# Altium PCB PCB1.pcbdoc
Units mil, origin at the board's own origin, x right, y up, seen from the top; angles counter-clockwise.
Board outline 3937 x 3937 mil, 2 copper layers (Top Layer, Bottom Layer), stack 62.2 mil thick; 14 components, 17 nets, 84 pads, 0 vias.
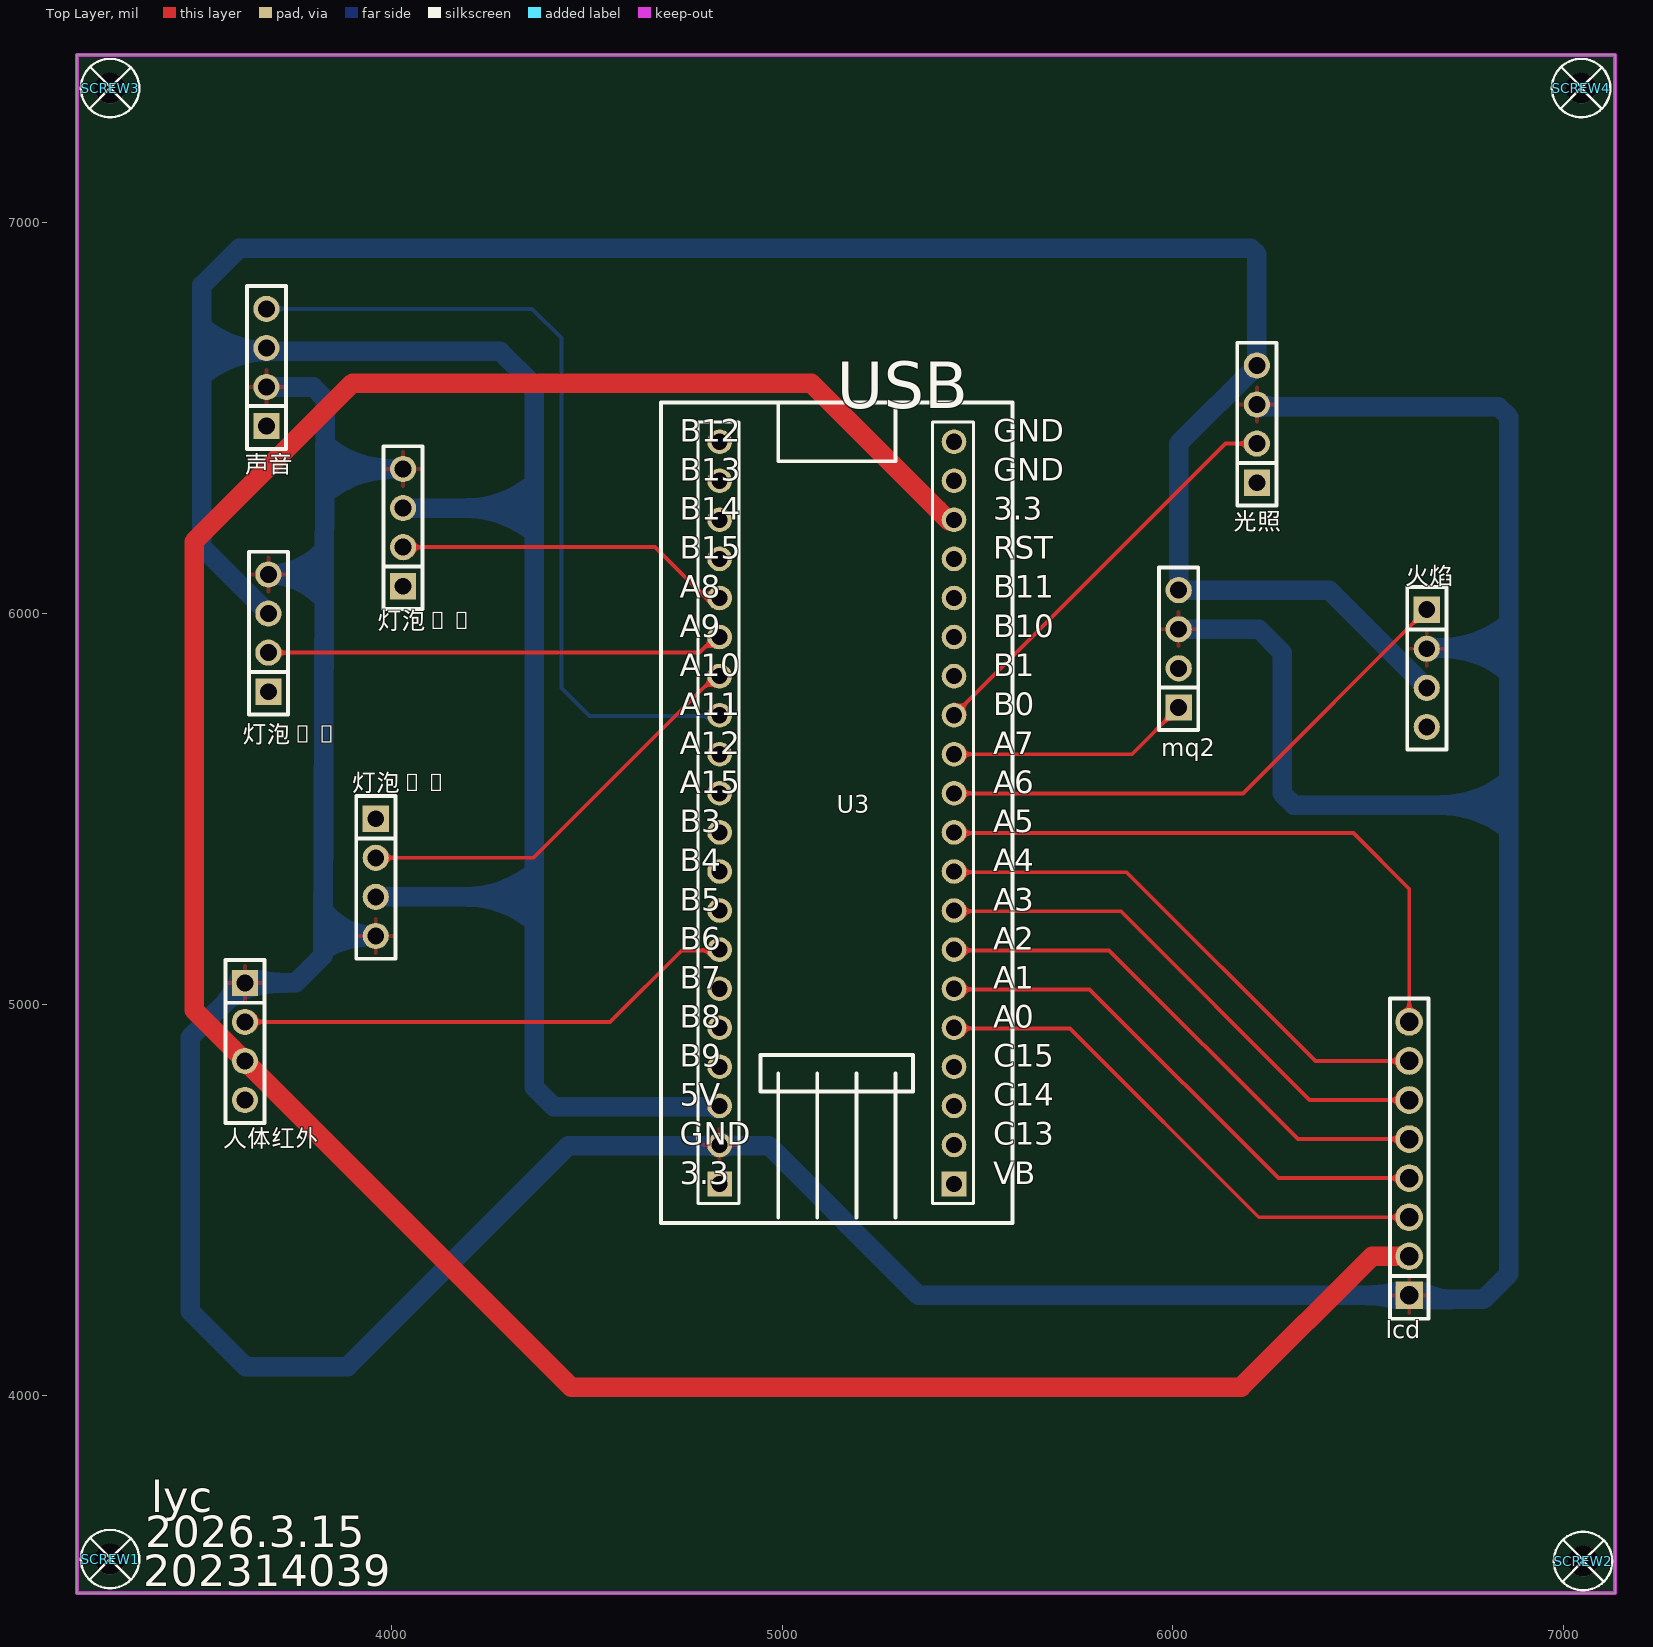
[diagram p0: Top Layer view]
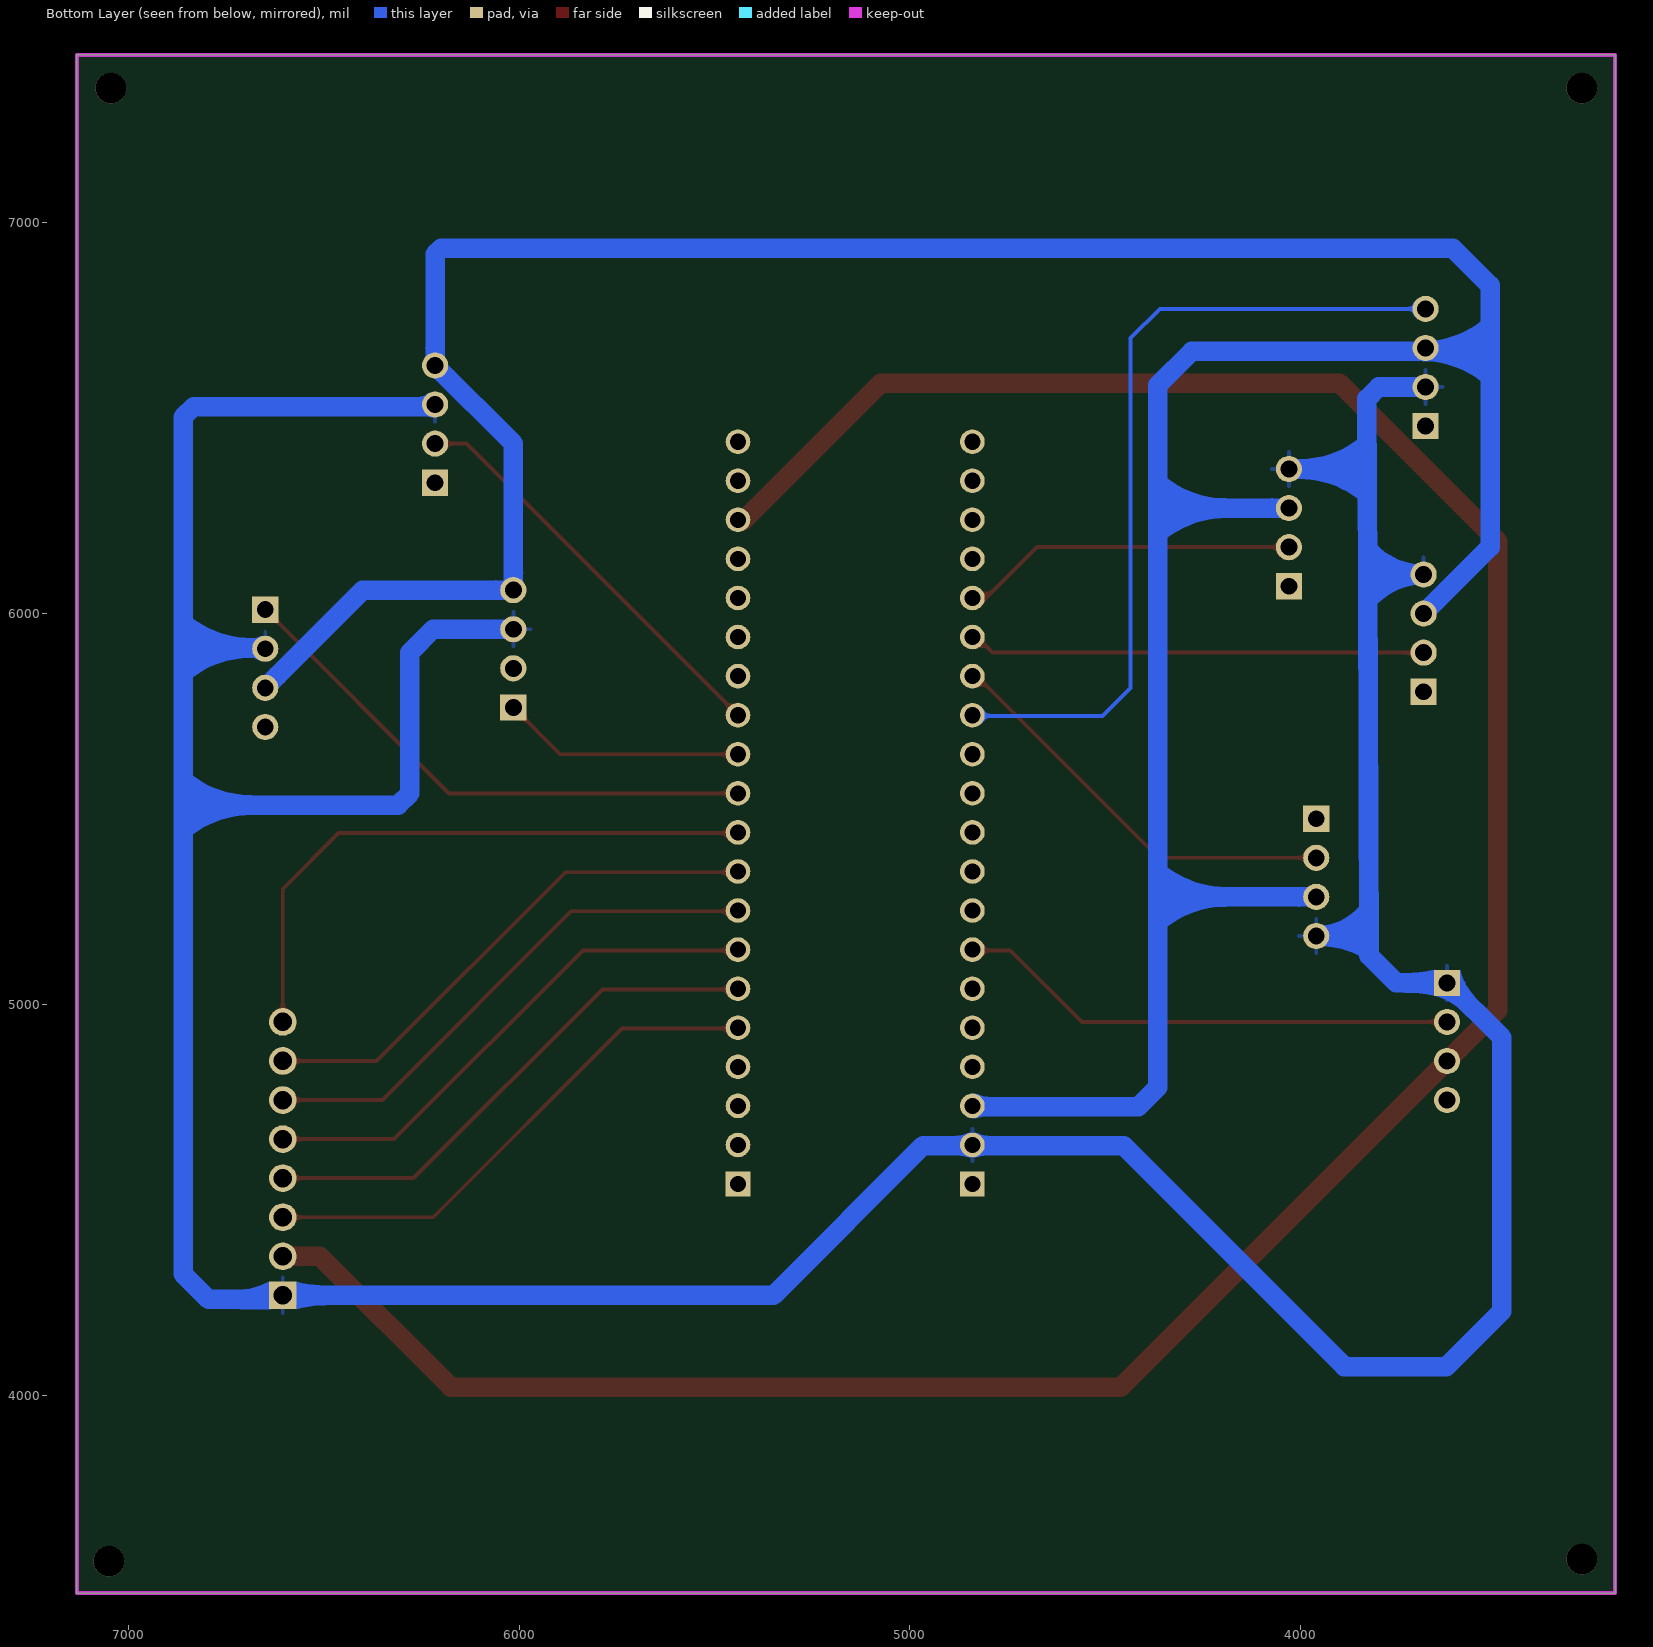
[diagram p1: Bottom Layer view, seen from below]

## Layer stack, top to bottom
Top Solder Mask Layer: solder mask 0.4, Dk 3.3
Top Layer: signal copper 1.4
Dielectric1: surface 59.4, FR4, Dk 4.5
Bottom Layer: signal copper 1.4
Bottom Solder Mask Layer: solder mask 0.4, Dk 3.3

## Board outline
3195,7430 3195,3493 7132,3493 7132,7430

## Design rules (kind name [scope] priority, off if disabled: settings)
BoardOutlineClearance copperThickness1oz [All] p0: genericclearance=10 ignorepadtopadclearanceinfootprint=FALSE except(0: Arc-SplitContinuation Track-SplitContinuation SMDPad-SplitContinuation THPad-SplitContinuation Via-SplitContinuation Fill-SplitContinuation Poly-SplitContinuation Region-SplitContinuation Text-SplitContinuation)
BoardOutlineClearance copperThickness2oz [All] p0: genericclearance=10 ignorepadtopadclearanceinfootprint=FALSE except(0: Arc-SplitContinuation Track-SplitContinuation SMDPad-SplitContinuation THPad-SplitContinuation Via-SplitContinuation Fill-SplitContinuation Poly-SplitContinuation Region-SplitContinuation Text-SplitContinuation)
BoardOutlineClearance Plane_innerPlane [All] p0: genericclearance=10 ignorepadtopadclearanceinfootprint=FALSE except(0: Arc-SplitContinuation Track-SplitContinuation SMDPad-SplitContinuation THPad-SplitContinuation Via-SplitContinuation Fill-SplitContinuation Poly-SplitContinuation Region-SplitContinuation Text-SplitContinuation)
BoardOutlineClearance Copper_copperRegion [All] p0: genericclearance=10 ignorepadtopadclearanceinfootprint=FALSE except(0: Arc-SplitContinuation Track-SplitContinuation SMDPad-SplitContinuation THPad-SplitContinuation Via-SplitContinuation Fill-SplitContinuation Poly-SplitContinuation Region-SplitContinuation Text-SplitContinuation)
BoardOutlineClearance otherClearance [All] p0: genericclearance=10 ignorepadtopadclearanceinfootprint=FALSE except(0: Arc-SplitContinuation Track-SplitContinuation SMDPad-SplitContinuation THPad-SplitContinuation Via-SplitContinuation Fill-SplitContinuation Poly-SplitContinuation Region-SplitContinuation Text-SplitContinuation)
Clearance copperThickness1oz [All] p1: gap=7 ignorepadtopadclearanceinfootprint=FALSE
Clearance copperThickness2oz [All] p1: gap=7 ignorepadtopadclearanceinfootprint=FALSE
Clearance Plane_innerPlane [All] p1: gap=7 ignorepadtopadclearanceinfootprint=FALSE
Clearance Copper_copperRegion [All] p1: gap=7 ignorepadtopadclearanceinfootprint=FALSE
Clearance otherClearance [All] p1: gap=7 ignorepadtopadclearanceinfootprint=FALSE
DiffPairsRouting differentialPair [All] p1: maxuncoupledlength=10 minlimit=6 maxlimit=Infinity mostfreqgap=6 toplayer_minwidth=5 toplayer_prefwidth=10 toplayer_maxwidth=100 bottomlayer_minwidth=5 bottomlayer_prefwidth=10 bottomlayer_maxwidth=100
PasteMaskExpansion pasteMaskExpansion [All] p1: expansion=0
PlaneConnect innerPlane [All] p1: planeconnectstyle=Relief reliefexpansion=20 reliefentries=4 reliefconductorwidth=10 reliefairgap=10
PolygonConnect copperRegion [All] p1: connectstyle=Relief reliefentries=4 reliefconductorwidth=10 polygonreliefangle="90 Angle" airgapwidth=10
RoutingVias viaSize [All] p1: viastyle="Through Hole" holewidth=12.0078 minholewidth=11.811 maxholewidth=248.0314 width=12.0078 minwidth=11.811 maxwidth=248.0314
SolderMaskExpansion solderMaskExpansion [IsVia] p1: useseparateexpansions=TRUE expansion=-1000 expansionbottom=-1000
SolderMaskExpansion solderMaskExpansion [All] p2: useseparateexpansions=TRUE expansion=2 expansionbottom=2
Width copperThickness1oz [All] p1: maxlimit=100 minlimit=5 preferedwidth=10
Width copperThickness2oz [All] p1: maxlimit=100 minlimit=8 preferedwidth=10

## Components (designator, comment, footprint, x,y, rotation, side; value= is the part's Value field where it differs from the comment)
lcd "lcd" HDR-TH_8P-P2.54-V-F-1 6605,4605 r90 top
mq2 "2.54-1*4P母" HDR-TH_4P-P2.54-V-F 6015,5910 r90 top
SCREW1 "" M2螺丝 3280,3580 r0 top
SCREW2 "" M2螺丝 7050,3575 r0 top
SCREW3 "" M2螺丝 3280,7345 r0 top
SCREW4 "" M2螺丝 7045,7345 r0 top
U3 "CW32F030C8最小系统板" STM32F103C8T6核心板 5140,5490 r0 top
人体红外 "2.54-1*4P母" HDR-TH_4P-P2.54-V-F 3625,4905 r270 top
光照 "光照" HDR-TH_4P-P2.54-V-F 6215,6485 r90 top
声音 "2.54-1*4P母" HDR-TH_4P-P2.54-V-F 3680,6630 r90 top
火焰 "火焰" HDR-TH_4P-P2.54-V-F 6650,5860 r270 top
灯泡-1 "2.54-1*4P母" HDR-TH_4P-P2.54-V-F 3960,5325 r270 top
灯泡-2 "2.54-1*4P母" HDR-TH_4P-P2.54-V-F 3685,5950 r90 top
灯泡-3 "2.54-1*4P母" HDR-TH_4P-P2.54-V-F 4030,6220 r90 top

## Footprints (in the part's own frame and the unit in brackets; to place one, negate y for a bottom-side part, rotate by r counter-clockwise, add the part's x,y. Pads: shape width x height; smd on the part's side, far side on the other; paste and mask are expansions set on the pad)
HDR-TH_4P-P2.54-V-F [mil]
  rect 66.9x66.9 hole 43.3: 1(-150,0)
  round 66.9 hole 43.3: 2(-50,0) 3(50,0) 4(150,0)
  silkscreen extent -208,-50 208,50
HDR-TH_8P-P2.54-V-F-1 [mil]
  rect 70.9x70.9 hole 47.2: 1(-350,0)
  round 70.9 hole 47.2: 2(-250,0) 3(-150,0) 4(-50,0) 5(50,0) 6(150,0) 7(250,0) 8(350,0)
  silkscreen extent -410,-49 410,49
M2螺丝 [mil]
  round 78.7 hole 78.7: 1(0,0)
  silkscreen extent -75,-75 75,75
STM32F103C8T6核心板 [mil]
  rect 63x63 hole 41.3 paste+4 mask+4: 1(300,-950) 40(-300,-950)
  round 63 hole 41.3 paste+4 mask+4: 2(300,-850) 3(300,-750) 4(300,-650) 5(300,-550) 6(300,-450) 7(300,-350) 8(300,-250) 9(300,-150) 10(300,-50) 11(300,50) 12(300,150) 13(300,250) 14(300,350) 15(300,450) 16(300,550) 17(300,650) 18(300,750) 19(300,850) 20(300,950) 21(-300,950) 22(-300,850) 23(-300,750) 24(-300,650) 25(-300,550) 26(-300,450) 27(-300,350) 28(-300,250) 29(-300,150) 30(-300,50) 31(-300,-50) 32(-300,-150) 33(-300,-250) 34(-300,-350) 35(-300,-450) 36(-300,-550) 37(-300,-650) 38(-300,-750) 39(-300,-850)
  silkscreen extent -450,-1050 450,1050

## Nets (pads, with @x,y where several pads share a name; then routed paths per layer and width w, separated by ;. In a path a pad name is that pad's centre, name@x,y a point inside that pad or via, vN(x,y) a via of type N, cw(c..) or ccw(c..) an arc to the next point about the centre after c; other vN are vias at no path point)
AO: mq2.1 U3.12 | length 624.7
  Top Layer w10: U3.12 5895,5640 mq2.1
BLK: lcd.8 U3.10 | length 1578.1
  Top Layer w10: U3.10@5426.2,5438.1 6461.9,5438.1 6605,5295 lcd.8
CS: lcd.7 U3.9 | length 1378.9
  Top Layer w10: U3.9@5426.2,5338.1 5881.9,5338.1 6365,4855 lcd.7
DC: lcd.6 U3.8 | length 1378.9
  Top Layer w10: U3.8@5426.2,5238.1 5866.9,5238.1 6350,4755 lcd.6
DO-1: U3.13 光照.2 | length 1062.9
  Top Layer w10: U3.13 6135,6435 光照.2
DO-2: U3.34 人体红外.2 | length 1277
  Top Layer w10: 人体红外.2 4559.8,4955 4743,5138.1 U3.34@4826.2,5138.1
DO-3: U3.11 火焰.1 | length 1404.7
  Top Layer w10: U3.11 6180,5540 火焰.1
DO-4: U3.28 声音.4 | length 2102
  Bottom Layer w10: 声音.4 4360,6780 4435,6705 4435,5810 4506.9,5738.1 U3.28@4826.2,5738.1
GND: lcd.1 mq2.3 U3.39 人体红外.1 光照.3 声音.2 火焰.2 灯泡-1.4 灯泡-2.4 灯泡-3.4 | length 11343.7
  Bottom Layer w50: 声音.2 3800,6580 3830.5,6549.5 3828.7,6099 ; 灯泡-2.4 3827.7,6100 3828.7,6099 ; 3835,5185 3845,5175 灯泡-1.4 ; 3840,6370 灯泡-3.4 ; mq2.3 6220,5960 6280,5900 6280,5540 6310,5510 6853,5510 6860,5517 ; 光照.3 6220,6530 6832.9,6530 6860,6502.9 6860,5910 ; 火焰.2 6652.1,5912.1 6857.9,5912.1 6860,5910 ; 3828.7,6099 3824.9,5124.9 3755,5055 人体红外.1 3485,4915 3485,4215 3627.1,4072.9 3887.9,4072.9 4453.1,4638.1 4826.2,4638.1 4966.2,4638.1 5349.4,4255 lcd.1 6615,4245 6795,4245 6860,4310 6860,5517 ; 6860,5517 6860,5910
PA8: U3.25 灯泡-3.2 | length 845
  Top Layer w10: 灯泡-3.2 4674.5,6170 U3.25@4816.3,6028.2
PA9: U3.26 灯泡-2.2 | length 1157
  Top Layer w10: 灯泡-2.2 4788.1,5900 U3.26@4826.2,5938.1
PA10: U3.27 灯泡-1.2 | length 1044
  Top Layer w10: 灯泡-1.2 4363.1,5375 U3.27@4816.3,5828.2
RES: lcd.5 U3.7 | length 1378.9
  Top Layer w10: U3.7@5426.2,5138.1 5836.9,5138.1 6320,4655 lcd.5
SCL: lcd.3 U3.5 | length 1378.9
  Top Layer w10: U3.5@5426.2,4938.1 5736.9,4938.1 6220,4455 lcd.3
SDA: lcd.4 U3.6 | length 1378.9
  Top Layer w10: U3.6@5426.2,5038.1 5786.9,5038.1 6270,4555 lcd.4
VCC-3: lcd.2 U3.18 人体红外.3 | length 7092.8
  Top Layer w50: U3.18@5426.2,6238.1 5074.4,6590 3900.7,6590 3495,6184.3 3495,4985 人体红外.3 4460,4020 6175,4020 6510,4355 lcd.2
VCC-5: mq2.4 U3.38 光照.4 声音.3 火焰.3 灯泡-1.3 灯泡-2.3 灯泡-3.3 | length 9263.8
  Bottom Layer w10: 声音.3 声音.3@3688.5,6671.5
  Bottom Layer w50: 灯泡-2.3 3515,6170 3515,6671.5 ; 灯泡-1.3 4352.6,5275 4365,5262.6 ; 灯泡-3.3 4353.8,6270 4365,6258.8 ; U3.38@4826.2,4738.1 4415,4738.1 4365,4788.1 4365,5262.6 ; 火焰.3 6400,6060 mq2.4 6015,6435 光照.4 6215,6920 6200,6935 3610,6935 3515,6840 3515,6671.5 ; 3515,6671.5 3688.5,6671.5 4278.5,6671.5 4365,6585 4365,6258.8 ; 4365,5262.6 4365,6258.8
pads on no net: mq2.2 SCREW1.1 SCREW2.1 SCREW3.1 SCREW4.1 U3.1 U3.2 U3.3 U3.4 U3.14 U3.15 U3.16 U3.17 U3.19 U3.20 U3.21 U3.22 U3.23 U3.24 U3.29 U3.30 U3.31 U3.32 U3.33 U3.35 U3.36 U3.37 U3.40 人体红外.4 光照.1 声音.1 火焰.4 灯泡-1.1 灯泡-2.1 灯泡-3.1

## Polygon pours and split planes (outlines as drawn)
GND on Top Layer (solid, remove dead copper, pour order 0): 3035,7515 3035,3265 7390,3265 7390,7515
GND on Bottom Layer (solid, remove dead copper, pour order 2): 3000,7655 3000,3000 7655,3000 7655,7655

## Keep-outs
Board Outline Layer:
  the board outline again, w10

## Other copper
Top Layer:
  region net DO-2: 3670.6,4960 3670.6,4950 3667.9,4949.9 3665.7,4949.5 3663.7,4949 3662.1,4948.3 3660.7,4947.4 3659.5,4946.3 3658.4,4945.1 3657.4,4943.7 3653.5,4937.3 3650.8,4933.7 3649.1,4931.8 3647.1,4929.9 3647.1,4980.1 3649.1,4978.2 3650.8,4976.3 3653.5,4972.7 3657.4,4966.3 3658.4,4964.9 3659.5,4963.7 3660.7,4962.6 3662.1,4961.7 3663.7,4961 3665.7,4960.5 3667.9,4960.1
  region net VCC-3: 3575.1,4869.5 3610.5,4904.9 3611.9,4903.4 3613.1,4901.8 3614.9,4898.9 3617.5,4893.8 3618.9,4891.8 3619.7,4890.9 3620.7,4890.1 3621.9,4889.5 3623.4,4889 3625.1,4888.6 3627.1,4888.4 3591.6,4852.9 3591.4,4854.9 3591,4856.6 3590.5,4858.1 3589.9,4859.3 3589.1,4860.3 3588.2,4861.1 3586.2,4862.5 3581.1,4865.1 3578.2,4866.9 3576.6,4868.1
  region net VCC-3: 3674.9,4840.5 3639.5,4805.1 3638.1,4806.6 3636.9,4808.2 3635.1,4811.1 3632.5,4816.2 3631.1,4818.2 3630.3,4819.1 3629.3,4819.9 3628.1,4820.5 3626.6,4821 3624.9,4821.4 3622.9,4821.6 3658.4,4857.1 3658.6,4855.1 3659,4853.4 3659.5,4851.9 3660.1,4850.7 3660.9,4849.7 3661.8,4848.9 3663.8,4847.5 3668.9,4844.9 3671.8,4843.1 3673.4,4841.9
  region net PA9: 3730.6,5905 3730.6,5895 3727.9,5894.9 3725.7,5894.5 3723.7,5894 3722.1,5893.3 3720.7,5892.4 3719.5,5891.3 3718.4,5890.1 3717.4,5888.7 3713.5,5882.3 3710.8,5878.7 3709.1,5876.8 3707.1,5874.9 3707.1,5925.1 3709.1,5923.2 3710.8,5921.3 3713.5,5917.7 3717.4,5911.3 3718.4,5909.9 3719.5,5908.7 3720.7,5907.6 3722.1,5906.7 3723.7,5906 3725.7,5905.5 3727.9,5905.1
  region net AO: 5983.3,5721.2 5976.2,5728.3 ccw(c5955,5744.2) 5981.5,5744.2 5999.2,5726.5 ccw(c5999.2,5700) 5983.3,5721.2
  region net DO-3: 6618.3,5971.2 6611.2,5978.3 ccw(c6590,5994.2) 6616.5,5994.2 6634.2,5976.5 ccw(c6634.2,5950) 6618.3,5971.2
  region net DO-1: 6169.4,6430 6169.4,6440 6172.1,6440.1 6174.3,6440.5 6176.3,6441 6177.9,6441.7 6179.3,6442.6 6180.5,6443.7 6181.6,6444.9 6182.6,6446.3 6186.5,6452.7 6189.2,6456.3 6190.9,6458.2 6192.9,6460.1 6192.9,6409.9 6190.9,6411.8 6189.2,6413.7 6186.5,6417.3 6182.6,6423.7 6181.6,6425.1 6180.5,6426.3 6179.3,6427.4 6177.9,6428.3 6176.3,6429 6174.3,6429.5 6172.1,6429.9
  region net VCC-3: 6556.8,4330 6556.8,4380 6560.8,4379.8 6564.3,4379.2 6567.4,4378.5 6570.2,4377.9 6573,4377.7 6574.3,4377.8 6575.7,4378.1 6577.1,4378.6 6578.5,4379.3 6580,4380.3 6581.6,4381.6 6581.6,4328.4 6580,4329.7 6578.5,4330.7 6577.1,4331.4 6575.7,4331.9 6574.3,4332.2 6573,4332.3 6570.2,4332.1 6567.4,4331.5 6564.3,4330.8 6560.8,4330.2
  region net SCL: 6556.8,4450 6556.8,4460 6559.6,4460.1 6562,4460.5 6564.1,4461.1 6565.8,4461.9 6567.3,4462.8 6568.5,4464 6569.7,4465.3 6570.7,4466.7 6574.8,4473.7 6576.1,4475.6 6577.7,4477.6 6579.4,4479.6 6581.6,4481.6 6581.6,4428.4 6579.4,4430.4 6577.7,4432.4 6576.1,4434.4 6574.8,4436.3 6570.7,4443.3 6569.7,4444.7 6568.5,4446 6567.3,4447.2 6565.8,4448.1 6564.1,4448.9 6562,4449.5 6559.6,4449.9
  region net SDA: 6556.8,4550 6556.8,4560 6559.6,4560.1 6562,4560.5 6564.1,4561.1 6565.8,4561.9 6567.3,4562.8 6568.5,4564 6569.7,4565.3 6570.7,4566.7 6574.8,4573.7 6576.1,4575.6 6577.7,4577.6 6579.4,4579.6 6581.6,4581.6 6581.6,4528.4 6579.4,4530.4 6577.7,4532.4 6576.1,4534.4 6574.8,4536.3 6570.7,4543.3 6569.7,4544.7 6568.5,4546 6567.3,4547.2 6565.8,4548.1 6564.1,4548.9 6562,4549.5 6559.6,4549.9
  region net RES: 6556.8,4650 6556.8,4660 6559.6,4660.1 6562,4660.5 6564.1,4661.1 6565.8,4661.9 6567.3,4662.8 6568.5,4664 6569.7,4665.3 6570.7,4666.7 6574.8,4673.7 6576.1,4675.6 6577.7,4677.6 6579.4,4679.6 6581.6,4681.6 6581.6,4628.4 6579.4,4630.4 6577.7,4632.4 6576.1,4634.4 6574.8,4636.3 6570.7,4643.3 6569.7,4644.7 6568.5,4646 6567.3,4647.2 6565.8,4648.1 6564.1,4648.9 6562,4649.5 6559.6,4649.9
  region net DC: 6556.8,4750 6556.8,4760 6559.6,4760.1 6562,4760.5 6564.1,4761.1 6565.8,4761.9 6567.3,4762.8 6568.5,4764 6569.7,4765.3 6570.7,4766.7 6574.8,4773.7 6576.1,4775.6 6577.7,4777.6 6579.4,4779.6 6581.6,4781.6 6581.6,4728.4 6579.4,4730.4 6577.7,4732.4 6576.1,4734.4 6574.8,4736.3 6570.7,4743.3 6569.7,4744.7 6568.5,4746 6567.3,4747.2 6565.8,4748.1 6564.1,4748.9 6562,4749.5 6559.6,4749.9
  region net CS: 6556.8,4850 6556.8,4860 6559.6,4860.1 6562,4860.5 6564.1,4861.1 6565.8,4861.9 6567.3,4862.8 6568.5,4864 6569.7,4865.3 6570.7,4866.7 6574.8,4873.7 6576.1,4875.6 6577.7,4877.6 6579.4,4879.6 6581.6,4881.6 6581.6,4828.4 6579.4,4830.4 6577.7,4832.4 6576.1,4834.4 6574.8,4836.3 6570.7,4843.3 6569.7,4844.7 6568.5,4846 6567.3,4847.2 6565.8,4848.1 6564.1,4848.9 6562,4849.5 6559.6,4849.9
  region net BLK: 6600,5003.2 6610,5003.2 6610.1,5000.4 6610.5,4998 6611.1,4995.9 6611.9,4994.2 6612.8,4992.7 6614,4991.5 6615.3,4990.3 6616.7,4989.3 6623.7,4985.2 6625.6,4983.9 6627.6,4982.3 6629.6,4980.6 6631.6,4978.4 6578.4,4978.4 6580.4,4980.6 6582.4,4982.3 6584.4,4983.9 6586.3,4985.2 6593.3,4989.3 6594.7,4990.3 6596,4991.5 6597.2,4992.7 6598.1,4994.2 6598.9,4995.9 6599.5,4998 6599.9,5000.4
  region net SCL: 5484.2,4943.1 5481.5,4933.1 5480.1,4933 5478.7,4932.6 5477.2,4931.9 5475.7,4931 5472.8,4928.7 5469.9,4925.9 5464.3,4919.9 5461.7,4917.3 5459.4,4915.2 5462.2,4962.4 5463.9,4960.6 5465.4,4958.8 5467.8,4955.3 5469.8,4952.1 5471.7,4949.2 5472.7,4947.9 5473.8,4946.7 5475,4945.7 5476.4,4944.8 5478,4944.1 5479.8,4943.6 5481.8,4943.3
  region net SDA: 5484.2,5043.1 5481.5,5033.1 5480.1,5033 5478.7,5032.6 5477.2,5031.9 5475.7,5031 5472.8,5028.7 5469.9,5025.9 5464.3,5019.9 5461.7,5017.3 5459.4,5015.2 5462.2,5062.4 5463.9,5060.6 5465.4,5058.8 5467.8,5055.3 5469.8,5052.1 5471.7,5049.2 5472.7,5047.9 5473.8,5046.7 5475,5045.7 5476.4,5044.8 5478,5044.1 5479.8,5043.6 5481.8,5043.3
  region net RES: 5484.2,5143.1 5481.5,5133.1 5480.1,5133 5478.7,5132.6 5477.2,5131.9 5475.7,5131 5472.8,5128.7 5469.9,5125.9 5464.3,5119.9 5461.7,5117.3 5459.4,5115.2 5462.2,5162.4 5463.9,5160.6 5465.4,5158.8 5467.8,5155.3 5469.8,5152.1 5471.7,5149.2 5472.7,5147.9 5473.8,5146.7 5475,5145.7 5476.4,5144.8 5478,5144.1 5479.8,5143.6 5481.8,5143.3
  region net DC: 5484.2,5243.1 5481.5,5233.1 5480.1,5233 5478.7,5232.6 5477.2,5231.9 5475.7,5231 5472.8,5228.7 5469.9,5225.9 5464.3,5219.9 5461.7,5217.3 5459.4,5215.2 5462.2,5262.4 5463.9,5260.6 5465.4,5258.8 5467.8,5255.3 5469.8,5252.1 5471.7,5249.2 5472.7,5247.9 5473.8,5246.7 5475,5245.7 5476.4,5244.8 5478,5244.1 5479.8,5243.6 5481.8,5243.3
  region net CS: 5484.2,5343.1 5481.5,5333.1 5480.1,5333 5478.7,5332.6 5477.2,5331.9 5475.7,5331 5472.8,5328.7 5469.9,5325.9 5464.3,5319.9 5461.7,5317.3 5459.4,5315.2 5462.2,5362.4 5463.9,5360.6 5465.4,5358.8 5467.8,5355.3 5469.8,5352.1 5471.7,5349.2 5472.7,5347.9 5473.8,5346.7 5475,5345.7 5476.4,5344.8 5478,5344.1 5479.8,5343.6 5481.8,5343.3
  region net BLK: 5484.2,5443.1 5481.5,5433.1 5480.1,5433 5478.7,5432.6 5477.2,5431.9 5475.7,5431 5472.8,5428.7 5469.9,5425.9 5464.3,5419.9 5461.7,5417.3 5459.4,5415.2 5462.2,5462.4 5463.9,5460.6 5465.4,5458.8 5467.8,5455.3 5469.8,5452.1 5471.7,5449.2 5472.7,5447.9 5473.8,5446.7 5475,5445.7 5476.4,5444.8 5478,5444.1 5479.8,5443.6 5481.8,5443.3
  region net DO-3: 5482.9,5545 5482.9,5535 5480.4,5534.9 5478.3,5534.6 5476.5,5534.1 5475,5533.4 5473.7,5532.6 5472.5,5531.6 5471.5,5530.4 5470.5,5529.2 5466.8,5523.2 5464.2,5519.8 5462.7,5518.1 5460.8,5516.4 5460.8,5563.6 5462.7,5561.9 5464.2,5560.2 5466.8,5556.8 5470.5,5550.8 5471.5,5549.6 5472.5,5548.4 5473.7,5547.4 5475,5546.6 5476.5,5545.9 5478.3,5545.4 5480.4,5545.1
  region net AO: 5482.9,5645 5482.9,5635 5480.4,5634.9 5478.3,5634.6 5476.5,5634.1 5475,5633.4 5473.7,5632.6 5472.5,5631.6 5471.5,5630.4 5470.5,5629.2 5466.8,5623.2 5464.2,5619.8 5462.7,5618.1 5460.8,5616.4 5460.8,5663.6 5462.7,5661.9 5464.2,5660.2 5466.8,5656.8 5470.5,5650.8 5471.5,5649.6 5472.5,5648.4 5473.7,5647.4 5475,5646.6 5476.5,5645.9 5478.3,5645.4 5480.4,5645.1
  region net DO-1: 5466.8,5773.9 5473.9,5766.8 5472.2,5765 5470.9,5763.3 5470,5761.6 5469.4,5760.1 5469.1,5758.5 5469,5757 5469,5755.5 5469.2,5753.9 5470.8,5747 5471.4,5742.9 5471.5,5740.6 5471.4,5738 5438,5771.4 5440.6,5771.5 5442.9,5771.4 5447,5770.8 5453.9,5769.2 5455.5,5769 5457,5769 5458.5,5769.1 5460.1,5769.4 5461.6,5770 5463.3,5770.9 5465,5772.2
  region net VCC-3: 5389.1,6240 5414.8,6285 5416.1,6283.5 5417.2,6282.1 5419.1,6279.1 5422,6273.7 5423.5,6271.6 5424.4,6270.8 5425.4,6270.2 5426.5,6269.9 5427.9,6269.7 5429.4,6269.8 5431.2,6270.2 5410.2,6229.9 5409.5,6231.4 5408.7,6232.6 5407.7,6233.6 5406.5,6234.3 5405.3,6234.9 5403.9,6235.3 5401,6235.8 5397.9,6236.2 5394.7,6236.8 5393.2,6237.3 5391.8,6238 5390.4,6238.8
  region net PA8: 4807.5,6030 4788,6063.6 4791.3,6060.8 4793,6059.5 4794.8,6058.4 4796.7,6057.5 4798.5,6056.7 4800.4,6056.1 4802.3,6055.7 4804.2,6055.5 4806.1,6055.5 4807.9,6055.7 4809.7,6056.2 4811.4,6056.9 4813.1,6057.9 4814.7,6059.1 4816.2,6060.6 4822.5,6013.8 4820.5,6015.3 4818.5,6017.2 4814.7,6021.5 4811.1,6026
  region net PA9: 4803.3,5908.2 4805.2,5924.2 4806.2,5925.4 4807,5926.7 4807.7,5928.1 4808.1,5929.7 4808.7,5933 4808.9,5936.5 4809.1,5943.7 4809.5,5947.1 4809.8,5948.8 4810.2,5950.3 4833.5,5909.2 4829.1,5910.2 4824.9,5911.3 4820.9,5912.3 4817.1,5912.9 4815.3,5913 4813.5,5913 4811.7,5912.8 4810,5912.4 4808.3,5911.7 4806.6,5910.8 4805,5909.6
  region net PA10: 4803.3,5808.2 4805.2,5824.2 4806.2,5825.4 4807,5826.7 4807.7,5828.1 4808.1,5829.7 4808.7,5833 4808.9,5836.5 4809.1,5843.7 4809.5,5847.1 4809.8,5848.8 4810.2,5850.3 4833.5,5809.2 4829.1,5810.2 4824.9,5811.3 4820.9,5812.3 4817.1,5812.9 4815.3,5813 4813.5,5813 4811.7,5812.8 4810,5812.4 4808.3,5811.7 4806.6,5810.8 4805,5809.6
  region net DO-2: 4798.5,5133.1 4795.8,5143.1 4798.2,5143.3 4800.2,5143.6 4802,5144.1 4803.6,5144.8 4805,5145.7 4806.2,5146.7 4807.3,5147.9 4808.3,5149.2 4810.2,5152.1 4812.2,5155.3 4814.6,5158.8 4816.1,5160.6 4817.8,5162.4 4820.6,5115.2 4818.3,5117.3 4815.7,5119.9 4810.1,5125.9 4807.2,5128.7 4804.3,5131 4802.8,5131.9 4801.3,5132.6 4799.9,5133
  region net PA10: 4005.6,5380 4005.6,5370 4002.9,5369.9 4000.7,5369.5 3998.7,5369 3997.1,5368.3 3995.7,5367.4 3994.5,5366.3 3993.4,5365.1 3992.4,5363.7 3988.5,5357.3 3985.8,5353.7 3984.1,5351.8 3982.1,5349.9 3982.1,5400.1 3984.1,5398.2 3985.8,5396.3 3988.5,5392.7 3992.4,5386.3 3993.4,5384.9 3994.5,5383.7 3995.7,5382.6 3997.1,5381.7 3998.7,5381 4000.7,5380.5 4002.9,5380.1
  region net PA8: 4075.6,6175 4075.6,6165 4072.9,6164.9 4070.7,6164.5 4068.7,6164 4067.1,6163.3 4065.7,6162.4 4064.5,6161.3 4063.4,6160.1 4062.4,6158.7 4058.5,6152.3 4055.8,6148.7 4054.1,6146.8 4052.1,6144.9 4052.1,6195.1 4054.1,6193.2 4055.8,6191.3 4058.5,6187.7 4062.4,6181.3 4063.4,6179.9 4064.5,6178.7 4065.7,6177.6 4067.1,6176.7 4068.7,6176 4070.7,6175.5 4072.9,6175.1
Bottom Layer:
  region net GND: 3733.5,5080 3733.5,5030 ccw(c3733.5,4693.5) 3658.5,5021.5 3658.5,5088.5 ccw(c3733.5,5416.5) 3733.5,5080
  region net GND: 3589.6,4984.3 3554.3,5019.6 ccw(c3457.3,5116.6) 3591.5,5088.5 3658.5,5021.5 ccw(c3686.6,4887.3) 3589.6,4984.3
  region net VCC-5: 3635.1,6014.5 3670.5,6049.9 3671.9,6048.4 3673.1,6046.8 3674.9,6043.9 3677.5,6038.8 3678.9,6036.8 3679.7,6035.9 3680.7,6035.1 3681.9,6034.5 3683.4,6034 3685.1,6033.6 3687.1,6033.4 3651.6,5997.9 3651.4,5999.9 3651,6001.6 3650.5,6003.1 3649.9,6004.3 3649.1,6005.3 3648.2,6006.1 3646.2,6007.5 3641.1,6010.1 3638.2,6011.9 3636.6,6013.1
  region net GND: 3730.6,6125 3730.6,6075 3728.5,6075.1 3726.6,6075.3 3723.2,6076.1 3717.8,6077.8 3715.3,6078.3 3714.1,6078.3 3712.8,6078.2 3711.5,6077.8 3710.2,6077.1 3708.7,6076.2 3707.1,6074.9 3707.1,6125.1 3708.7,6123.8 3710.2,6122.9 3711.5,6122.2 3712.8,6121.8 3714.1,6121.7 3715.3,6121.7 3717.8,6122.2 3723.2,6123.9 3726.6,6124.7 3728.5,6124.9
  region net GND: 3725.6,6605 3725.6,6555 3723.5,6555.1 3721.6,6555.3 3718.2,6556.1 3712.8,6557.8 3710.3,6558.3 3709.1,6558.3 3707.8,6558.2 3706.5,6557.8 3705.2,6557.1 3703.7,6556.2 3702.1,6554.9 3702.1,6605.1 3703.7,6603.8 3705.2,6602.9 3706.5,6602.2 3707.8,6601.8 3709.1,6601.7 3710.3,6601.7 3712.8,6602.2 3718.2,6603.9 3721.6,6604.7 3723.5,6604.9
  region net VCC-5: 3732.5,6696.5 3719.9,6646.5 3718.4,6646.6 3717,6646.8 3713.9,6647.7 3707.8,6650.1 3704.8,6651.2 3701.9,6651.8 3700.5,6651.9 3699.1,6651.8 3697.8,6651.5 3696.5,6650.9 3709.1,6696.6 3710.2,6694.9 3711.3,6693.7 3712.4,6692.8 3713.5,6692.3 3714.7,6692.1 3715.9,6692.1 3717.2,6692.3 3718.6,6692.7 3724.7,6695.1 3728.4,6696.1 3730.4,6696.4
  region net VCC-5: 3640.1,6646.5 3627.5,6696.5 3629.6,6696.4 3631.6,6696.1 3635.3,6695.1 3641.4,6692.7 3642.8,6692.3 3644.1,6692.1 3645.3,6692.1 3646.5,6692.3 3647.6,6692.8 3648.7,6693.7 3649.8,6694.9 3650.9,6696.6 3663.5,6650.9 3662.2,6651.5 3660.9,6651.8 3659.5,6651.9 3658.1,6651.8 3655.2,6651.2 3652.2,6650.1 3646.1,6647.7 3643,6646.8 3641.6,6646.6
  region net DO-4: 3725.6,6785 3725.6,6775 3722.9,6774.9 3720.7,6774.5 3718.7,6774 3717.1,6773.3 3715.7,6772.4 3714.5,6771.3 3713.4,6770.1 3712.4,6768.7 3708.5,6762.3 3705.8,6758.7 3704.1,6756.8 3702.1,6754.9 3702.1,6805.1 3704.1,6803.2 3705.8,6801.3 3708.5,6797.7 3712.4,6791.3 3713.4,6789.9 3714.5,6788.7 3715.7,6787.6 3717.1,6786.7 3718.7,6786 3720.7,6785.5 3722.9,6785.1
  region net GND: 6060.6,5985 6060.6,5935 6058.5,5935.1 6056.6,5935.3 6053.2,5936.1 6047.8,5937.8 6045.3,5938.3 6044.1,5938.3 6042.8,5938.2 6041.5,5937.8 6040.2,5937.1 6038.7,5936.2 6037.1,5934.9 6037.1,5985.1 6038.7,5983.8 6040.2,5982.9 6041.5,5982.2 6042.8,5981.8 6044.1,5981.7 6045.3,5981.7 6047.8,5982.2 6053.2,5983.9 6056.6,5984.7 6058.5,5984.9
  region net VCC-5: 5990,6105.6 6040,6105.6 6039.9,6103.5 6039.7,6101.6 6038.9,6098.2 6037.2,6092.8 6036.7,6090.3 6036.7,6089.1 6036.8,6087.8 6037.2,6086.5 6037.9,6085.2 6038.8,6083.7 6040.1,6082.1 5989.9,6082.1 5991.2,6083.7 5992.1,6085.2 5992.8,6086.5 5993.2,6087.8 5993.3,6089.1 5993.3,6090.3 5992.8,6092.8 5991.1,6098.2 5990.3,6101.6 5990.1,6103.5
  region net VCC-5: 6060.6,6085 6060.6,6035 6058.5,6035.1 6056.6,6035.3 6053.2,6036.1 6047.8,6037.8 6045.3,6038.3 6044.1,6038.3 6042.8,6038.2 6041.5,6037.8 6040.2,6037.1 6038.7,6036.2 6037.1,6034.9 6037.1,6085.1 6038.7,6083.8 6040.2,6082.9 6041.5,6082.2 6042.8,6081.8 6044.1,6081.7 6045.3,6081.7 6047.8,6082.2 6053.2,6083.9 6056.6,6084.7 6058.5,6084.9
  region net GND: 6682.5,5937.1 6686.4,5887.1 6682.9,5886.9 6679.8,5886.4 6677,5885.6 6674.4,5884.6 6669.2,5882.1 6666.3,5880.6 6663,5879.2 6659.1,5942.2 6665.3,5940.3 6670.7,5938.7 6673.3,5938 6676.1,5937.5 6679.2,5937.2
  region net VCC-5: 6600.1,5824.5 6635.5,5859.9 6636.9,5858.4 6638.1,5856.8 6639.9,5853.9 6642.5,5848.8 6643.9,5846.8 6644.7,5845.9 6645.7,5845.1 6646.9,5844.5 6648.4,5844 6650.1,5843.6 6652.1,5843.4 6616.6,5807.9 6616.4,5809.9 6616,5811.6 6615.5,5813.1 6614.9,5814.3 6614.1,5815.3 6613.2,5816.1 6611.2,5817.5 6606.1,5820.1 6603.2,5821.9 6601.6,5823.1
  region net GND: 6253.8,6555 6244.3,6505 6238.2,6504.7 6232.5,6504.1 6226.8,6503.1 6220.9,6502.1 6230.3,6564.7 6233.6,6562.9 6236.5,6561.2 6241.6,6558 6244.2,6556.8 6246.9,6555.8 6250.1,6555.2
  region net VCC-5: 6200.5,6585.1 6165.1,6620.5 6166.6,6621.9 6168.2,6623.1 6171.1,6624.9 6176.2,6627.5 6178.2,6628.9 6179.1,6629.7 6179.9,6630.7 6180.5,6631.9 6181,6633.4 6181.4,6635.1 6181.6,6637.1 6217.1,6601.6 6215.1,6601.4 6213.4,6601 6211.9,6600.5 6210.7,6599.9 6209.7,6599.1 6208.9,6598.2 6207.5,6596.2 6204.9,6591.1 6203.1,6588.2 6201.9,6586.6
  region net VCC-5: 6190,6680.6 6240,6680.6 6239.9,6678.5 6239.7,6676.6 6238.9,6673.2 6237.2,6667.8 6236.7,6665.3 6236.7,6664.1 6236.8,6662.8 6237.2,6661.5 6237.9,6660.2 6238.8,6658.7 6240.1,6657.1 6189.9,6657.1 6191.2,6658.7 6192.1,6660.2 6192.8,6661.5 6193.2,6662.8 6193.3,6664.1 6193.3,6665.3 6192.8,6667.8 6191.1,6673.2 6190.3,6676.6 6190.1,6678.5
  region net GND: 6494.6,4230 6494.6,4280 ccw(c6494.6,4554.8) 6569.6,4290.4 6569.6,4219.6 ccw(c6494.6,3955.2) 6494.6,4230
  region net GND: 6715.4,4270 6715.4,4220 ccw(c6715.4,-2275.3) 6640.4,4219.6 6640.4,4290.4 ccw(c6715.4,4417.9) 6715.4,4270
  region net DO-4: 4798.5,5733.1 4795.8,5743.1 4798.2,5743.3 4800.2,5743.6 4802,5744.1 4803.6,5744.8 4805,5745.7 4806.2,5746.7 4807.3,5747.9 4808.3,5749.2 4810.2,5752.1 4812.2,5755.3 4814.6,5758.8 4816.1,5760.6 4817.8,5762.4 4820.6,5715.2 4818.3,5717.3 4815.7,5719.9 4810.1,5725.9 4807.2,5728.7 4804.3,5731 4802.8,5731.9 4801.3,5732.6 4799.9,5733
  region net VCC-5: 4804.1,4713.1 4800.4,4763.1 4803.8,4763.2 4806.7,4763.5 4809.4,4763.8 4811.7,4764.3 4815.7,4765.5 4819.3,4766.9 4822.8,4768.3 4826.8,4769.7 4829.1,4770.3 4831.8,4770.8 4834.8,4771.2 4838.1,4771.4 4841.9,4708.6 4835.5,4708.4 4830.6,4708.8 4826.6,4709.5 4823,4710.4 4819.4,4711.4 4815.3,4712.3 4810.4,4712.9
  region net GND: 4879.6,4663.1 4875.9,4613.1 4869.6,4612.9 4864.7,4612.3 4860.6,4611.4 4857,4610.4 4853.4,4609.5 4849.4,4608.8 4844.5,4608.4 4838.1,4608.6 4841.9,4671.4 4845.2,4671.2 4848.2,4670.8 4850.9,4670.3 4853.2,4669.7 4857.2,4668.3 4860.7,4666.9 4864.3,4665.5 4868.3,4664.3 4870.6,4663.8 4873.3,4663.5 4876.2,4663.2
  region net GND: 4804.1,4613.1 4800.4,4663.1 4803.8,4663.2 4806.7,4663.5 4809.4,4663.8 4811.7,4664.3 4815.7,4665.5 4819.3,4666.9 4822.8,4668.3 4826.8,4669.7 4829.1,4670.3 4831.8,4670.8 4834.8,4671.2 4838.1,4671.4 4841.9,4608.6 4835.5,4608.4 4830.6,4608.8 4826.6,4609.5 4823,4610.4 4819.4,4611.4 4815.3,4612.3 4810.4,4612.9
  region net VCC-5: 4005.6,5300 4005.6,5250 4003.5,5250.1 4001.6,5250.3 3998.2,5251.1 3992.8,5252.8 3990.3,5253.3 3989.1,5253.3 3987.8,5253.2 3986.5,5252.8 3985.2,5252.1 3983.7,5251.2 3982.1,5249.9 3982.1,5300.1 3983.7,5298.8 3985.2,5297.9 3986.5,5297.2 3987.8,5296.8 3989.1,5296.7 3990.3,5296.7 3992.8,5297.2 3998.2,5298.9 4001.6,5299.7 4003.5,5299.9
  region net GND: 3914.4,5150 3914.4,5200 3916.5,5199.9 3918.4,5199.7 3921.8,5198.9 3927.2,5197.2 3929.7,5196.7 3930.9,5196.7 3932.2,5196.8 3933.5,5197.2 3934.8,5197.9 3936.3,5198.8 3937.9,5200.1 3937.9,5149.9 3936.3,5151.2 3934.8,5152.1 3933.5,5152.8 3932.2,5153.2 3930.9,5153.3 3929.7,5153.3 3927.2,5152.8 3921.8,5151.1 3918.4,5150.3 3916.5,5150.1
  region net VCC-5: 4075.6,6295 4075.6,6245 4073.5,6245.1 4071.6,6245.3 4068.2,6246.1 4062.8,6247.8 4060.3,6248.3 4059.1,6248.3 4057.8,6248.2 4056.5,6247.8 4055.2,6247.1 4053.7,6246.2 4052.1,6244.9 4052.1,6295.1 4053.7,6293.8 4055.2,6292.9 4056.5,6292.2 4057.8,6291.8 4059.1,6291.7 4060.3,6291.7 4062.8,6292.2 4068.2,6293.9 4071.6,6294.7 4073.5,6294.9
  region net GND: 3984.4,6345 3984.4,6395 3986.5,6394.9 3988.4,6394.7 3991.8,6393.9 3997.2,6392.2 3999.7,6391.7 4000.9,6391.7 4002.2,6391.8 4003.5,6392.2 4004.8,6392.9 4006.3,6393.8 4007.9,6395.1 4007.9,6344.9 4006.3,6346.2 4004.8,6347.1 4003.5,6347.8 4002.2,6348.2 4000.9,6348.3 3999.7,6348.3 3997.2,6347.8 3991.8,6346.1 3988.4,6345.3 3986.5,6345.1
  region net GND: 3685,6125 ccw(c3685,6291.6) 3804,6175 3828.7,6099 3803.4,6025 ccw(c3685,5909.8) 3685,6075
  region net GND: 4004.7,6345 ccw(c4004.7,6094.4) 3854.5,6295 3829.8,6370.1 3855.1,6445 ccw(c4004.9,6644.4) 4004.9,6395 4004.7,6345
  region net GND: 3960,5150 ccw(c3960,4897.1) 3849.9,5124.8 3825.1,5175.1 3850.4,5250 ccw(c3960,5345.2) 3960,5200
  region net VCC-5: 4190,5250 cw(c4190,5000) 4340,5200 4365,5262.6 4340,5350 cw(c4190,5550) 4190,5300 4190,5250
  region net VCC-5: 4190,6295 ccw(c4190,6545) 4340,6345 4365,6258.8 4340,6195 ccw(c4190,5995) 4190,6245 4190,6295
  region net VCC-5: 3688.5,6646.5 ccw(c3688.5,6401) 3540,6596.5 3515,6671.5 3540,6746.5 ccw(c3688.5,6942) 3688.5,6696.5 3688.5,6646.5
  region net GND: 6685,5535 ccw(c6685,5785) 6835,5585 6860,5517 6835,5435 ccw(c6685,5235) 6685,5485 6685,5535
  region net GND: 6685,5937.1 ccw(c6685,6187.1) 6835,5987.1 6860,5910 6835,5837.1 ccw(c6685,5637.1) 6685,5887.1 6685,5937.1

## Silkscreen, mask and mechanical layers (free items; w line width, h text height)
Top Silkscreen Layer:
  text "lyc" at 3385,3700 h80
  text "2026.3.15" at 3370,3610 h80
  text "202314039" at 3365,3510 h80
